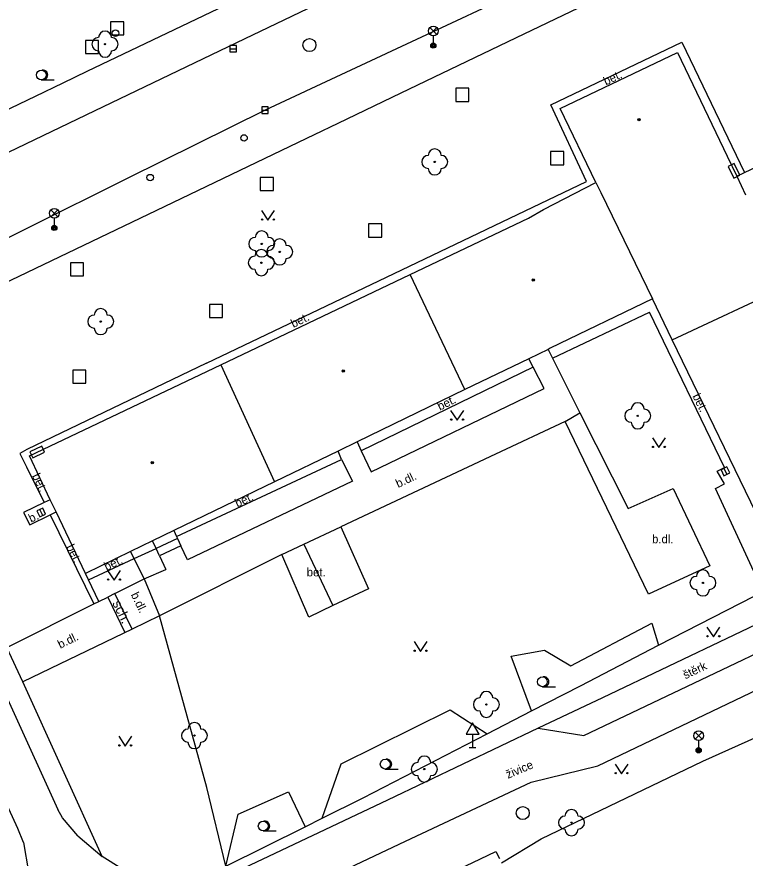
# Model space of a CAD drawing. Extents: x -595546 to -593986, y -1160845 to -1159202.
# Drawn here: x -595433.4 to -595377.5, y -1159994.7 to -1159930.2 of the extents above; entities that cross this region are included whole.
import ezdxf

# ---------------------------------------------------------------- set-up
doc = ezdxf.new("R2010")
doc.units = 0
for name, color, linetype in [('Level 22', 7, 'Continuous'), ('Level 24', 7, 'Continuous'), ('Level 26', 7, 'Continuous'), ('Level 27', 7, 'Continuous'), ('Level 28', 7, 'Continuous'), ('Level 33', 7, 'Continuous'), ('Level 34', 7, 'Continuous'), ('Level 36', 7, 'Continuous'), ('Level 39', 7, 'Continuous'), ('Specificka linie pasportu komunikaci', 7, 'Continuous'), ('TM - budovy zdene_ betonove - VP', 7, 'Continuous'), ('TM - chodniky - VP', 7, 'Continuous'), ('TM - hranice souvisleho porostu (skupiny stromu_ kere)', 7, 'Continuous'), ('TM - komunikace - VP', 7, 'Continuous'), ('TM - plot drateny_ kovovy - VP', 7, 'Continuous'), ('TM - popis povrchu', 7, 'Continuous'), ('TM - poznamka', 7, 'Continuous'), ('TM - rozhrani ploch obecne - VP', 7, 'Continuous'), ('TM - schody - VP', 7, 'Continuous'), ('TM - vjezd na pozemek', 7, 'Continuous')]:
    doc.layers.add(name, color=color, linetype=linetype)

msp = doc.modelspace()

# ---------------------------------------------------------------- linework, layer by layer
at = {"layer": 'Level 22'}
for centre in [(-595426.65, -1159932.25), (-595401.36, -1159941.29), (-595414.63, -1159947.58), (-595413.25, -1159948.19), (-595414.66, -1159949.02), (-595426.98, -1159953.54), (-595385.79, -1159960.77), (-595380.79, -1159973.59), (-595397.4, -1159982.92), (-595419.79, -1159985.31), (-595402.16, -1159987.88), (-595390.87, -1159991.99)]:
    msp.add_circle(centre, 0.05, dxfattribs=at)
for centre, start, end in [((-595426.65, -1159931.75), 0, 180), ((-595427.15, -1159932.25), 90, 270), ((-595426.15, -1159932.25), 270, 90), ((-595426.65, -1159932.75), 180, 0), ((-595401.36, -1159940.79), 0, 180), ((-595401.86, -1159941.29), 90, 270), ((-595400.86, -1159941.29), 270, 90), ((-595401.36, -1159941.79), 180, 0), ((-595415.13, -1159947.58), 90, 270), ((-595414.63, -1159947.08), 0, 180), ((-595414.13, -1159947.58), 270, 90), ((-595413.75, -1159948.19), 90, 270), ((-595413.25, -1159947.69), 0, 180), ((-595412.75, -1159948.19), 270, 90), ((-595414.66, -1159948.52), 0, 180), ((-595414.63, -1159948.08), 180, 0), ((-595415.16, -1159949.02), 90, 270), ((-595414.16, -1159949.02), 270, 90), ((-595413.25, -1159948.69), 180, 0), ((-595414.66, -1159949.52), 180, 0), ((-595426.98, -1159953.04), 0, 180), ((-595427.48, -1159953.54), 90, 270), ((-595426.48, -1159953.54), 270, 90), ((-595426.98, -1159954.04), 180, 0), ((-595385.79, -1159960.27), 0, 180), ((-595386.29, -1159960.77), 90, 270), ((-595385.29, -1159960.77), 270, 90), ((-595385.79, -1159961.27), 180, 0), ((-595380.79, -1159973.09), 0, 180), ((-595381.29, -1159973.59), 90, 270), ((-595380.29, -1159973.59), 270, 90), ((-595380.79, -1159974.09), 180, 0), ((-595397.4, -1159982.42), 0, 180), ((-595397.9, -1159982.92), 90, 270), ((-595396.9, -1159982.92), 270, 90), ((-595397.4, -1159983.42), 180, 0), ((-595419.79, -1159984.81), 0, 180), ((-595420.29, -1159985.31), 90, 270), ((-595419.29, -1159985.31), 270, 90), ((-595419.79, -1159985.81), 180, 0), ((-595402.16, -1159987.38), 0, 180), ((-595402.66, -1159987.88), 90, 270), ((-595401.66, -1159987.88), 270, 90), ((-595402.16, -1159988.38), 180, 0), ((-595390.87, -1159991.49), 0, 180), ((-595391.37, -1159991.99), 90, 270), ((-595390.37, -1159991.99), 270, 90), ((-595390.87, -1159992.49), 180, 0)]:
    msp.add_arc(centre, 0.5, start, end, dxfattribs=at)
at = {"layer": 'Level 24'}
for points in [[(-595377.966, -1159942.313), (-595378.397, -1159941.41), (-595378.848, -1159941.626), (-595378.418, -1159942.528)], [(-595431.507, -1159963.106), (-595432.41, -1159963.537), (-595432.195, -1159963.988), (-595431.292, -1159963.558)]]:
    msp.add_lwpolyline(points, close=True, dxfattribs=at)
at = {"layer": 'Level 26'}
for points in [[(-595426.22, -1159931.54), (-595425.22, -1159931.54), (-595425.22, -1159930.54), (-595426.22, -1159930.54)], [(-595428.16, -1159932.96), (-595427.16, -1159932.96), (-595427.16, -1159931.96), (-595428.16, -1159931.96)], [(-595399.74, -1159936.64), (-595398.74, -1159936.64), (-595398.74, -1159935.64), (-595399.74, -1159935.64)], [(-595392.47, -1159941.5), (-595391.47, -1159941.5), (-595391.47, -1159940.5), (-595392.47, -1159940.5)], [(-595414.74, -1159943.47), (-595413.74, -1159943.47), (-595413.74, -1159942.47), (-595414.74, -1159942.47)], [(-595406.43, -1159947.05), (-595405.43, -1159947.05), (-595405.43, -1159946.05), (-595406.43, -1159946.05)], [(-595429.29, -1159950.04), (-595428.29, -1159950.04), (-595428.29, -1159949.04), (-595429.29, -1159949.04)], [(-595418.63, -1159953.23), (-595417.63, -1159953.23), (-595417.63, -1159952.23), (-595418.63, -1159952.23)], [(-595429.11, -1159958.26), (-595428.11, -1159958.26), (-595428.11, -1159957.26), (-595429.11, -1159957.26)]]:
    msp.add_lwpolyline(points, close=True, dxfattribs=at)
at = {"layer": 'Level 27'}
for p, q in [((-595417.07, -1159932.6), (-595416.57, -1159932.6)), ((-595414.63, -1159937.31), (-595414.13, -1159937.31)), ((-595378.951, -1159965.255), (-595379.169, -1159964.805)), ((-595431.432, -1159968.416), (-595431.648, -1159967.964))]:
    msp.add_line(p, q, dxfattribs=at)
for points in [[(-595417.07, -1159932.85), (-595416.57, -1159932.85), (-595416.57, -1159932.35), (-595417.07, -1159932.35)], [(-595414.63, -1159937.56), (-595414.13, -1159937.56), (-595414.13, -1159937.06), (-595414.63, -1159937.06)], [(-595378.726, -1159965.146), (-595378.944, -1159964.696), (-595379.394, -1159964.914), (-595379.176, -1159965.364)], [(-595431.207, -1159968.308), (-595431.422, -1159967.857), (-595431.873, -1159968.072), (-595431.658, -1159968.523)]]:
    msp.add_lwpolyline(points, close=True, dxfattribs=at)
for centre in [(-595410.97, -1159932.32), (-595394.61, -1159991.25)]:
    msp.add_circle(centre, 0.5, dxfattribs=at)
at = {"layer": 'Level 28'}
for centre in [(-595425.84, -1159931.41), (-595415.99, -1159939.45), (-595423.19, -1159942.49)]:
    msp.add_circle(centre, 0.25, dxfattribs=at)
at = {"layer": 'Level 33'}
for p, q in [((-595401.735, -1159931.5), (-595401.205, -1159930.97)), ((-595401.735, -1159930.97), (-595401.205, -1159931.5)), ((-595401.47, -1159931.61), (-595401.47, -1159932.36)), ((-595430.805, -1159945.49), (-595430.275, -1159944.96)), ((-595430.805, -1159944.96), (-595430.275, -1159945.49)), ((-595430.54, -1159945.6), (-595430.54, -1159946.35)), ((-595381.385, -1159985.58), (-595380.855, -1159985.05)), ((-595381.385, -1159985.05), (-595380.855, -1159985.58)), ((-595381.12, -1159985.69), (-595381.12, -1159986.44))]:
    msp.add_line(p, q, dxfattribs=at)
for centre, radius in [((-595401.47, -1159931.235), 0.375), ((-595401.47, -1159932.36), 0.2), ((-595401.47, -1159932.36), 0.145), ((-595401.47, -1159932.36), 0.0876), ((-595430.54, -1159945.225), 0.375), ((-595430.54, -1159946.35), 0.2), ((-595430.54, -1159946.35), 0.145), ((-595430.54, -1159946.35), 0.0876), ((-595381.12, -1159985.315), 0.375), ((-595381.12, -1159986.44), 0.2), ((-595381.12, -1159986.44), 0.145), ((-595381.12, -1159986.44), 0.0876)]:
    msp.add_circle(centre, radius, dxfattribs=at)
at = {"layer": 'Level 34'}
for p, q in [((-595398.46, -1159985.202), (-595398.46, -1159986.22)), ((-595398.71, -1159986.22), (-595398.21, -1159986.22))]:
    msp.add_line(p, q, dxfattribs=at)
msp.add_lwpolyline([(-595398.96, -1159985.202), (-595397.96, -1159985.202), (-595398.46, -1159984.336)], close=True, dxfattribs=at)
at = {"layer": 'Level 36'}
for p, q in [((-595431.54, -1159934.985), (-595430.54, -1159934.985)), ((-595393.1, -1159981.555), (-595392.1, -1159981.555)), ((-595405.16, -1159987.875), (-595404.16, -1159987.875)), ((-595414.52, -1159992.625), (-595413.52, -1159992.625))]:
    msp.add_line(p, q, dxfattribs=at)
for points in [[(-595414.65, -1159945.01), (-595414.15, -1159945.76), (-595413.65, -1159945.01)], [(-595400.14, -1159960.36), (-595399.64, -1159961.11), (-595399.14, -1159960.36)], [(-595384.67, -1159962.46), (-595384.17, -1159963.21), (-595383.67, -1159962.46)], [(-595426.46, -1159972.64), (-595425.96, -1159973.39), (-595425.46, -1159972.64)], [(-595380.49, -1159976.99), (-595379.99, -1159977.74), (-595379.49, -1159976.99)], [(-595402.95, -1159978.1), (-595402.45, -1159978.85), (-595401.95, -1159978.1)], [(-595425.6, -1159985.36), (-595425.1, -1159986.11), (-595424.6, -1159985.36)], [(-595387.53, -1159987.49), (-595387.03, -1159988.24), (-595386.53, -1159987.49)]]:
    msp.add_lwpolyline(points, dxfattribs=at)
for centre, radius in [((-595431.54, -1159934.61), 0.375), ((-595414.6, -1159945.71), 0.05), ((-595413.701, -1159945.71), 0.05), ((-595400.09, -1159961.06), 0.05), ((-595399.191, -1159961.06), 0.05), ((-595384.62, -1159963.16), 0.05), ((-595383.721, -1159963.16), 0.05), ((-595426.41, -1159973.34), 0.05), ((-595425.511, -1159973.34), 0.05), ((-595380.44, -1159977.69), 0.05), ((-595379.541, -1159977.69), 0.05), ((-595402.9, -1159978.8), 0.05), ((-595402.001, -1159978.8), 0.05), ((-595393.1, -1159981.18), 0.375), ((-595425.55, -1159986.06), 0.05), ((-595424.651, -1159986.06), 0.05), ((-595405.16, -1159987.5), 0.375), ((-595387.48, -1159988.19), 0.05), ((-595386.581, -1159988.19), 0.05), ((-595414.52, -1159992.25), 0.375)]:
    msp.add_circle(centre, radius, dxfattribs=at)
for centre in [(-595431.415, -1159934.61), (-595392.975, -1159981.18), (-595405.035, -1159987.5), (-595414.395, -1159992.25)]:
    msp.add_arc(centre, 0.375, 260.40593, 99.59407, dxfattribs=at)
at = {"layer": 'Level 39'}
for centre, radius in [((-595385.7, -1159938.05), 0.09), ((-595385.7, -1159938.05), 0.0398), ((-595393.8, -1159950.35), 0.09), ((-595393.8, -1159950.35), 0.0398), ((-595408.38, -1159957.33), 0.09), ((-595408.38, -1159957.33), 0.0398), ((-595423.03, -1159964.37), 0.09), ((-595423.03, -1159964.37), 0.0398)]:
    msp.add_circle(centre, radius, dxfattribs=at)
at = {"layer": 'Specificka linie pasportu komunikaci'}
msp.add_lwpolyline([(-595424.57, -1159977.14), (-595425.89, -1159974.4)], dxfattribs=at)
at = {"layer": 'TM - budovy zdene_ betonove - VP'}
for points in [[(-595391.73, -1159937.2), (-595382.74, -1159932.88)], [(-595382.74, -1159932.88), (-595378.94, -1159940.85)], [(-595389.01, -1159942.86), (-595391.73, -1159937.2)], [(-595378.94, -1159940.85), (-595378.2, -1159942.38)], [(-595378.2, -1159942.38), (-595377.52, -1159943.81)], [(-595393.03, -1159944.93), (-595389.01, -1159942.86)], [(-595389.01, -1159942.86), (-595388.62, -1159943.64)], [(-595388.62, -1159943.64), (-595384.67, -1159951.8)], [(-595394.17, -1159945.6), (-595393.03, -1159944.93)], [(-595403.25, -1159949.93), (-595394.17, -1159945.6)], [(-595417.77, -1159956.85), (-595403.25, -1159949.93)], [(-595399.04, -1159958.76), (-595403.25, -1159949.93)], [(-595383.15, -1159954.95), (-595374.18, -1159950.75)], [(-595384.67, -1159951.8), (-595392.5, -1159955.59)], [(-595383.15, -1159954.95), (-595384.67, -1159951.8)], [(-595375.92, -1159969.88), (-595383.15, -1159954.95)], [(-595392.66, -1159955.67), (-595394.14, -1159956.39)], [(-595392.5, -1159955.59), (-595392.66, -1159955.67)], [(-595394.14, -1159956.39), (-595399.04, -1159958.76)], [(-595432.45, -1159963.85), (-595417.77, -1159956.85)], [(-595417.77, -1159956.85), (-595413.64, -1159965.83)], [(-595399.04, -1159958.76), (-595407.32, -1159962.77)], [(-595407.32, -1159962.77), (-595408.77, -1159963.47)], [(-595430.85, -1159967.21), (-595432.45, -1159963.85)], [(-595408.77, -1159963.47), (-595413.64, -1159965.83)], [(-595413.64, -1159965.83), (-595421.38, -1159969.58)], [(-595430.4, -1159968.14), (-595430.85, -1159967.21)], [(-595428.15, -1159972.86), (-595430.4, -1159968.14)], [(-595421.38, -1159969.58), (-595423, -1159970.36)], [(-595423, -1159970.36), (-595424.69, -1159971.18)], [(-595424.69, -1159971.18), (-595428.15, -1159972.86)]]:
    msp.add_lwpolyline(points, dxfattribs=at)
at = {"layer": 'TM - chodniky - VP'}
for points in [[(-595394.51, -1159931.46), (-595381.94, -1159925.42)], [(-595416.3, -1159928.71), (-595428.04, -1159934.36)], [(-595403.94, -1159935.99), (-595394.51, -1159931.46)], [(-595428.04, -1159934.36), (-595429.88, -1159935.24)], [(-595429.88, -1159935.24), (-595432.02, -1159936.27)], [(-595408.78, -1159938.32), (-595403.94, -1159935.99)], [(-595432.02, -1159936.27), (-595442.74, -1159941.41)], [(-595410.59, -1159939.19), (-595408.78, -1159938.32)], [(-595423.31, -1159945.29), (-595410.59, -1159939.19)], [(-595377.61, -1159942.1), (-595370.7, -1159938.83)], [(-595378.2, -1159942.38), (-595377.61, -1159942.1)], [(-595439.44, -1159953.02), (-595423.31, -1159945.29)], [(-595392.66, -1159955.67), (-595392.32, -1159956.35)], [(-595393.81, -1159957.04), (-595394.14, -1159956.39)], [(-595392.32, -1159956.35), (-595390.22, -1159960.54)], [(-595392.97, -1159958.68), (-595393.81, -1159957.04)], [(-595406.24, -1159965.08), (-595392.97, -1159958.68)], [(-595391.36, -1159961.21), (-595390.22, -1159960.54)], [(-595391.36, -1159961.21), (-595396.71, -1159963.71)], [(-595407.32, -1159962.77), (-595407, -1159963.45)], [(-595408.5, -1159964.12), (-595408.77, -1159963.47)], [(-595396.71, -1159963.71), (-595408.57, -1159969.29)], [(-595407, -1159963.45), (-595406.24, -1159965.08)], [(-595408.5, -1159964.12), (-595407.68, -1159965.78)], [(-595407.68, -1159965.78), (-595420.33, -1159971.81)], [(-595421.38, -1159969.58), (-595421.17, -1159970.02)], [(-595411.39, -1159970.62), (-595408.57, -1159969.29)], [(-595422.74, -1159970.94), (-595423, -1159970.36)], [(-595421.17, -1159970.02), (-595421.1, -1159970.18)], [(-595421.1, -1159970.18), (-595420.84, -1159970.74)], [(-595422.47, -1159971.51), (-595422.74, -1159970.94)], [(-595420.33, -1159971.81), (-595420.84, -1159970.74)], [(-595413.1, -1159971.42), (-595411.39, -1159970.62)], [(-595422.47, -1159971.51), (-595421.98, -1159972.56)], [(-595413.1, -1159971.42), (-595422.46, -1159976.12)], [(-595423.66, -1159973.29), (-595421.98, -1159972.56)], [(-595425.89, -1159974.4), (-595423.66, -1159973.29)], [(-595427.12, -1159975.02), (-595426.44, -1159974.68)], [(-595425.89, -1159974.4), (-595426.44, -1159974.68)], [(-595434.18, -1159978.56), (-595427.5, -1159975.21)], [(-595427.5, -1159975.21), (-595427.12, -1159975.02)], [(-595422.46, -1159976.12), (-595424.57, -1159977.14)], [(-595424.57, -1159977.14), (-595432.95, -1159981.19)], [(-595426.87, -1159994.59), (-595432.95, -1159981.19)], [(-595407.7, -1159999.47), (-595396.67, -1159994.2), (-595396.39, -1159994.74)]]:
    msp.add_lwpolyline(points, dxfattribs=at)
at = {"layer": 'TM - hranice souvisleho porostu (skupiny stromu_ kere)'}
for points in [[(-595393.95, -1159983.42), (-595395.49, -1159979.21), (-595392.93, -1159978.75), (-595390.93, -1159979.96), (-595384.72, -1159976.69), (-595384.19, -1159978.36)], [(-595410, -1159991.65), (-595408.55, -1159987.48), (-595400.18, -1159983.34), (-595397.35, -1159985.17)], [(-595417.39, -1159995.32), (-595416.45, -1159991.34), (-595412.57, -1159989.62), (-595411.31, -1159992.3)]]:
    msp.add_lwpolyline(points, dxfattribs=at)
at = {"layer": 'TM - komunikace - VP'}
for points in [[(-595385.7, -1159917.35), (-595415.35, -1159931.57), (-595426.79, -1159937.06), (-595441.39, -1159944.07)], [(-595383.04, -1159922.66), (-595414.38, -1159937.31), (-595424.9, -1159942.53), (-595440.33, -1159950.2)], [(-595444.2, -1159960.38), (-595430.28, -1159990.97)], [(-595433.34, -1159992.43), (-595447.28, -1159962.05)], [(-595403.6, -1159993.4), (-595393.96, -1159988.88), (-595388.84, -1159987.62), (-595371.91, -1159979.53), (-595361.225, -1159974.729)], [(-595393.42, -1159984.75), (-595389.93, -1159985.3), (-595379.87, -1159980.51), (-595370.02, -1159975.81)], [(-595393.42, -1159984.75), (-595404.98, -1159990.27)], [(-595404.98, -1159990.27), (-595416.49, -1159995.7)], [(-595428.73, -1159993), (-595429.92, -1159991.61), (-595430.28, -1159990.97)], [(-595432.91, -1159993.51), (-595433.34, -1159992.43)], [(-595432.91, -1159993.51), (-595432.51, -1159995.76), (-595432.59, -1159997.73)], [(-595428.73, -1159993), (-595426.87, -1159994.59)], [(-595409.32, -1159996.13), (-595403.6, -1159993.4)], [(-595423.23, -1159996.22), (-595425.36, -1159995.54), (-595426.87, -1159994.59)]]:
    msp.add_lwpolyline(points, dxfattribs=at)
at = {"layer": 'TM - plot drateny_ kovovy - VP'}
for points in [[(-595424.42, -1159971.73), (-595424.69, -1159971.18)], [(-595423.66, -1159973.29), (-595424.42, -1159971.73)], [(-595384.19, -1159978.36), (-595374.76, -1159973.54), (-595372.05, -1159972.2)], [(-595418.85, -1159989.28), (-595422.46, -1159976.12)], [(-595393.95, -1159983.42), (-595390.19, -1159981.48), (-595384.19, -1159978.36)], [(-595393.19, -1159993.23), (-595380.8, -1159987.27), (-595370.59, -1159982.68)], [(-595397.35, -1159985.17), (-595393.95, -1159983.42)], [(-595410, -1159991.65), (-595406.84, -1159990.08), (-595397.35, -1159985.17)], [(-595417.39, -1159995.32), (-595418.85, -1159989.28)], [(-595411.31, -1159992.3), (-595410, -1159991.65)], [(-595417.39, -1159995.32), (-595411.31, -1159992.3)]]:
    msp.add_lwpolyline(points, dxfattribs=at)
at = {"layer": 'TM - rozhrani ploch obecne - VP'}
for points in [[(-595418.86, -1159956.74), (-595405.05, -1159950.14), (-595389.73, -1159942.8), (-595392.46, -1159936.9), (-595382.4, -1159932.11), (-595377.61, -1159942.1)], [(-595392.32, -1159956.35), (-595384.88, -1159952.82)], [(-595379.13, -1159964.73), (-595384.88, -1159952.82)], [(-595418.86, -1159956.74), (-595432.66, -1159963.36), (-595433.19, -1159963.66), (-595432.68, -1159964.68), (-595431.31, -1159967.43)], [(-595393.81, -1159957.04), (-595407, -1159963.45)], [(-595390.22, -1159960.54), (-595386.52, -1159967.89), (-595383.08, -1159966.35)], [(-595384.96, -1159974.46), (-595391.36, -1159961.21)], [(-595421.17, -1159970.02), (-595408.5, -1159964.12)], [(-595372.8, -1159970.69), (-595375.23, -1159971.94), (-595376.89, -1159972.71), (-595379.83, -1159966.35), (-595379.13, -1159966), (-595379.69, -1159965.03), (-595379.13, -1159964.73)], [(-595383.08, -1159966.35), (-595380.26, -1159972.27)], [(-595431.31, -1159967.43), (-595432.9, -1159968.19)], [(-595430.85, -1159967.21), (-595431.31, -1159967.43)], [(-595432.9, -1159968.19), (-595432.43, -1159969.13)], [(-595432.43, -1159969.13), (-595430.86, -1159968.36)], [(-595430.86, -1159968.36), (-595430.4, -1159968.14)], [(-595430.86, -1159968.36), (-595427.5, -1159975.21)], [(-595408.57, -1159969.29), (-595406.43, -1159974.05)], [(-595424.42, -1159971.73), (-595422.74, -1159970.94)], [(-595420.84, -1159970.74), (-595422.47, -1159971.51)], [(-595411.39, -1159970.62), (-595409.17, -1159975.33)], [(-595411.02, -1159976.21), (-595413.1, -1159971.42)], [(-595427.91, -1159973.36), (-595424.42, -1159971.73)], [(-595380.26, -1159972.27), (-595384.96, -1159974.46)], [(-595427.91, -1159973.36), (-595428.15, -1159972.86)], [(-595427.12, -1159975.02), (-595427.91, -1159973.36)], [(-595406.43, -1159974.05), (-595409.17, -1159975.33)], [(-595409.17, -1159975.33), (-595411.02, -1159976.21)], [(-595373.38, -1159975.21), (-595388.5, -1159982.41), (-595393.42, -1159984.75)], [(-595432.95, -1159981.19), (-595434.18, -1159978.56)]]:
    msp.add_lwpolyline(points, dxfattribs=at)
at = {"layer": 'TM - schody - VP'}
for points in [[(-595421.1, -1159970.18), (-595422.74, -1159970.94)], [(-595426.44, -1159974.68), (-595425.13, -1159977.4)], [(-595424.57, -1159977.13), (-595425.89, -1159974.4)]]:
    msp.add_lwpolyline(points, dxfattribs=at)
at = {"layer": 'TM - vjezd na pozemek'}
for points in [[(-595423.66, -1159973.29), (-595422.46, -1159976.12)], [(-595396.24, -1159995.06), (-595393.19, -1159993.23)]]:
    msp.add_lwpolyline(points, dxfattribs=at)

# ---------------------------------------------------------------- texts
at = {"layer": 'TM - popis povrchu'}
for s, rotation, p in [('bet.', 25.46113, (-595388.23, -1159935.43)), ('bet.', 25.46113, (-595412.21, -1159954.03)), ('bet.', 25.91856, (-595400.97, -1159960.38)), ('bet.', 295.78242, (-595381.61, -1159959.25)), ('bet.', 295.46335, (-595432.26, -1159965.37)), ('b.dl.', 25.19647, (-595404.17, -1159966.31)), ('bet.', 24.92524, (-595416.5, -1159967.81)), ('b.', 26.12545, (-595432.32, -1159968.98)), ('bet.', 296.12846, (-595429.64, -1159970.82)), ('bet.', 25.08359, (-595426.54, -1159972.67)), ('b.dl.', 295.79801, (-595424.69, -1159974.49)), ('b.dl.', 25.79801, (-595430.09, -1159978.65)), ('štěrk', 25.43588, (-595382.13, -1159980.99)), ('živice', 23.12041, (-595395.74, -1159988.63))]:
    msp.add_text(s, height=0.65, rotation=rotation, dxfattribs=at).set_placement(p)
for s, p in [('b.dl.', (-595384.69, -1159970.55)), ('bet.', (-595411.18, -1159973.09))]:
    msp.add_text(s, height=0.65, dxfattribs=at).set_placement(p)
at = {"layer": 'TM - poznamka'}
msp.add_text('sch.', height=0.75, rotation=295.79801, dxfattribs=at).set_placement((-595426.11, -1159975.14))

doc.saveas('drawing.dxf')
